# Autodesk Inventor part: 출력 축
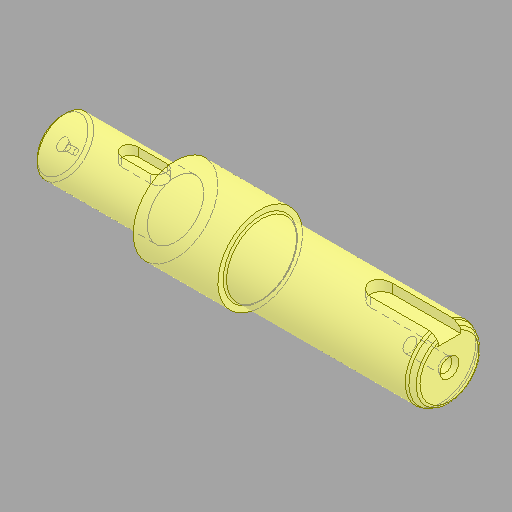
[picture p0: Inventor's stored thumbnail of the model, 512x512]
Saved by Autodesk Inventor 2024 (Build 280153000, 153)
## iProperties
Created: 2025-11
Part Number: 출력 축
Material: 강철, 탄소
Document SubType Name: Modeling
Designer: Edu09
Density: 7.85 g/cm^3
Appearance: 기본값
Author: jhkim
Sending System: Autodesk Inventor 2026
Preprocessor: ST-DEVELOPER v20.1
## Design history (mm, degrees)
feature "솔리드1"
node "솔리드2"
